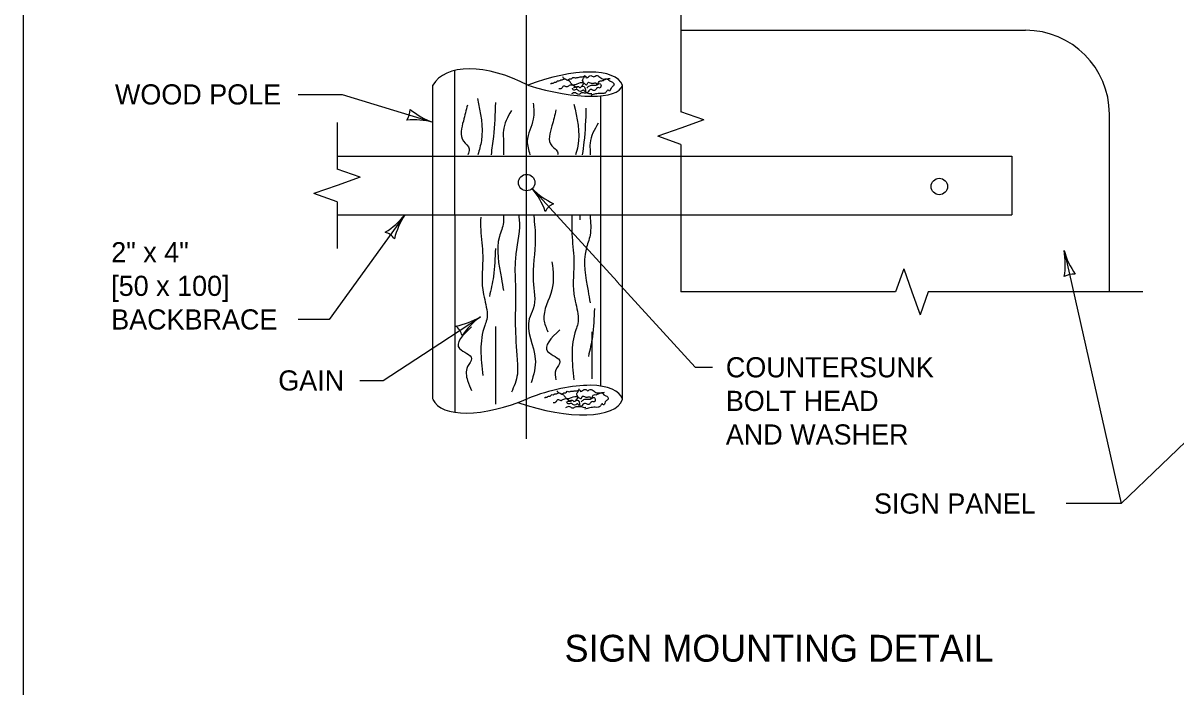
# Model space of a CAD drawing. Extents: x 49991.4 to 50021, y 49987.6 to 50011.4.
# Drawn here: x 50000.336 to 50003.769, y 50003.463 to 50005.439 of the extents above; entities that cross this region are included whole.
import ezdxf

# ---------------------------------------------------------------- set-up
doc = ezdxf.new("R2010")
doc.units = 0
for name, color, linetype in [('Level 1', 7, 'Continuous'), ('Level 2', 7, 'Continuous'), ('Level 3', 7, 'Continuous'), ('Level 4', 7, 'Continuous'), ('Level 5', 7, 'Continuous'), ('Level 6', 7, 'Continuous')]:
    doc.layers.add(name, color=color, linetype=linetype)

msp = doc.modelspace()

# ---------------------------------------------------------------- linework, layer by layer
at = {"layer": 'Level 1'}
for p, q in [((50002.2949, 50005.4172), (50003.321, 50005.4172)), ((50001.6211, 50005.0423), (50001.6211, 50005.2974)), ((50001.5562, 50005.0423), (50001.5562, 50005.2533)), ((50002.0562, 50005.0423), (50002.0562, 50005.2219)), ((50002.1211, 50005.0423), (50002.1211, 50005.2533)), ((50003.571, 50004.6385), (50003.571, 50005.1672)), ((50001.2707, 50005.0423), (50002.2949, 50005.0423)), ((50001.2707, 50004.868), (50002.2949, 50004.868)), ((50001.5562, 50004.3188), (50001.5562, 50004.868)), ((50001.6211, 50004.868), (50001.6211, 50004.2803)), ((50001.9934, 50004.8648), (50001.9942, 50004.8526)), ((50002.0562, 50004.3583), (50002.0562, 50004.868)), ((50002.1211, 50004.3189), (50002.1211, 50004.868))]:
    msp.add_line(p, q, dxfattribs=at)
msp.add_lwpolyline([(50008.6146, 50011.2628), (50000.3356, 50011.2628), (50000.3356, 50000.0624), (50008.6146, 50000.0624)], close=True, dxfattribs=at)
for centre in [(50001.8354, 50004.9639), (50003.0644, 50004.9522)]:
    msp.add_circle(centre, 0.0245, dxfattribs=at)
msp.add_arc((50003.321, 50005.1672), 0.25, 0, 90, dxfattribs=at)
for centre, major_axis, ratio, start_param, end_param in [((50001.7754, 50005.1356), (-0.2192, 0.1177), 0.537084, 4.712389, 6.283185), ((50001.8754, 50005.1582), (0.2457, 0.0951), 0.387082, 0, 1.570796), ((50001.8626, 50005.3321), (0.2585, -0.0788), 0.304673, 4.712389, 6.283185), ((50001.8747, 50004.226), (0.2457, 0.0951), 0.387082, 6.260938, 7.84809), ((50001.7958, 50004.4224), (-0.2396, -0.1036), 0.420526, 0.000916, 1.570796), ((50001.8445, 50004.4166), (0.2766, -0.0977), 0.384401, 4.720139, 6.283852)]:
    msp.add_ellipse(centre, major_axis=major_axis, ratio=ratio, start_param=start_param, end_param=end_param, dxfattribs=at)
for points in [[(50001.9083, 50005.2565), (50001.9083, 50005.2594), (50001.914, 50005.2594), (50001.9183, 50005.2623), (50001.9227, 50005.2623), (50001.927, 50005.2666), (50001.9313, 50005.2666), (50001.9371, 50005.2695), (50001.9414, 50005.2695), (50001.9501, 50005.2723), (50001.9587, 50005.2681), (50001.9631, 50005.2723), (50001.9688, 50005.2723), (50001.9731, 50005.2767), (50001.9804, 50005.2753), (50001.9846, 50005.2767), (50001.989, 50005.2767), (50001.9948, 50005.2781), (50001.9991, 50005.2781), (50002.0049, 50005.2796), (50002.0121, 50005.2796), (50002.0121, 50005.2767), (50002.0164, 50005.2767), (50002.0221, 50005.281), (50002.0308, 50005.281), (50002.0351, 50005.2781), (50002.0394, 50005.281), (50002.0509, 50005.2796), (50002.0611, 50005.2723), (50002.0726, 50005.2723), (50002.0784, 50005.2709), (50002.0827, 50005.2666), (50002.0913, 50005.2623), (50002.0957, 50005.2551), (50002.0942, 50005.2522), (50002.087, 50005.245), (50002.0812, 50005.2363), (50002.0784, 50005.2392), (50002.0726, 50005.2335), (50002.0654, 50005.2291), (50002.0567, 50005.2291), (50002.0409, 50005.2277), (50002.0265, 50005.2233)], [(50001.9313, 50005.2436), (50001.94, 50005.245), (50001.9458, 50005.2522), (50001.9544, 50005.2493), (50001.9631, 50005.2536), (50001.976, 50005.2551), (50001.9861, 50005.258), (50002.0063, 50005.2594), (50002.0149, 50005.2551), (50002.0193, 50005.2623), (50002.025, 50005.2608), (50002.0336, 50005.2594), (50002.0423, 50005.2594), (50002.0438, 50005.2551), (50002.0495, 50005.258), (50002.0539, 50005.258), (50002.0567, 50005.2493), (50002.0539, 50005.245), (50002.0495, 50005.2464), (50002.0438, 50005.2436), (50002.038, 50005.2378), (50002.025, 50005.2407), (50002.0164, 50005.232), (50002.0049, 50005.2306), (50001.9991, 50005.2306), (50001.9904, 50005.2263), (50001.9818, 50005.2306), (50001.9688, 50005.2277)], [(50001.9861, 50005.245), (50001.9688, 50005.258), (50001.9631, 50005.2652), (50001.9486, 50005.2723), (50001.9428, 50005.2781)], [(50002.0005, 50005.2508), (50002.0049, 50005.2608), (50002.002, 50005.2681), (50002.0063, 50005.2767), (50002.0091, 50005.2839)], [(50002.0149, 50005.245), (50002.0207, 50005.2508), (50002.0322, 50005.2536), (50002.0452, 50005.2551), (50002.0539, 50005.2666), (50002.0596, 50005.2666), (50002.0639, 50005.2681), (50002.074, 50005.2723), (50002.0842, 50005.2738)], [(50001.9746, 50005.2464), (50001.9804, 50005.2478), (50001.9904, 50005.2493), (50001.9933, 50005.2464), (50001.9991, 50005.2493), (50002.0063, 50005.2493), (50002.0091, 50005.2349), (50002.0034, 50005.2392), (50001.9991, 50005.2363), (50001.9919, 50005.2363), (50001.9846, 50005.2407), (50001.976, 50005.2392), (50001.9731, 50005.2421), (50001.9717, 50005.245)], [(50002.0106, 50005.2349), (50002.0207, 50005.2291), (50002.0294, 50005.2291)], [(50001.6588, 50005.1946), (50001.6469, 50005.147), (50001.6469, 50005.0875), (50001.6647, 50005.0638), (50001.6602, 50005.0468)], [(50001.6888, 50005.2136), (50001.7007, 50005.0887), (50001.6902, 50005.0468)], [(50001.7423, 50005.2017), (50001.7364, 50005.1006), (50001.7293, 50005.0468)], [(50001.8552, 50005.2003), (50001.8552, 50005.1527), (50001.8374, 50005.0873), (50001.8454, 50005.0468)], [(50001.9761, 50005.1977), (50001.988, 50005.0728), (50001.9814, 50005.0468)], [(50001.7899, 50005.1779), (50001.7661, 50005.1185), (50001.7661, 50005.0947), (50001.7661, 50005.0468)], [(50001.9226, 50005.1799), (50001.9107, 50005.1323), (50001.9107, 50005.0728), (50001.9285, 50005.0491), (50001.9278, 50005.0468)], [(50002.0121, 50005.1856), (50002.0061, 50005.0845), (50002.0011, 50005.0468)], [(50002.0481, 50005.1406), (50002.0243, 50005.0812), (50002.0243, 50005.0574), (50002.0243, 50005.0468)], [(50001.6986, 50004.8611), (50001.6986, 50004.8235), (50001.7046, 50004.7462), (50001.7046, 50004.6451), (50001.7165, 50004.5857), (50001.7165, 50004.5559), (50001.7105, 50004.5381), (50001.7046, 50004.3895)], [(50001.7661, 50004.8648), (50001.7661, 50004.845), (50001.7542, 50004.8034), (50001.7601, 50004.6785), (50001.7661, 50004.6429)], [(50001.812, 50004.8648), (50001.8137, 50004.845), (50001.8018, 50004.738), (50001.8018, 50004.6607), (50001.8018, 50004.5834), (50001.8018, 50004.5299), (50001.8077, 50004.4229), (50001.8077, 50004.3932), (50001.7899, 50004.3397)], [(50001.8565, 50004.8648), (50001.8611, 50004.796), (50001.8552, 50004.6712), (50001.8552, 50004.5879), (50001.8433, 50004.5582), (50001.8611, 50004.4393), (50001.8493, 50004.3679)], [(50001.9701, 50004.8648), (50001.9701, 50004.8112), (50001.9761, 50004.734), (50001.9761, 50004.6329), (50001.988, 50004.5735), (50001.988, 50004.5437), (50001.982, 50004.5259), (50001.9761, 50004.3772)], [(50002.0243, 50004.8648), (50002.0243, 50004.8076), (50002.0124, 50004.766), (50002.0184, 50004.6412), (50002.0243, 50004.6056)], [(50001.7423, 50004.7677), (50001.7364, 50004.6845), (50001.7245, 50004.625)], [(50001.9107, 50004.728), (50001.9107, 50004.6448), (50001.8869, 50004.5556), (50001.8988, 50004.5199)], [(50002.0373, 50004.589), (50002.0313, 50004.5058), (50002.0194, 50004.4463)], [(50001.6714, 50004.535), (50001.6357, 50004.4696), (50001.6714, 50004.4399), (50001.6595, 50004.4161), (50001.6595, 50004.3745), (50001.6714, 50004.3448)], [(50001.7423, 50004.5358), (50001.7423, 50004.5002), (50001.7423, 50004.4407), (50001.7423, 50004.3753), (50001.7423, 50004.3456), (50001.7423, 50004.3159), (50001.7423, 50004.304)], [(50001.9345, 50004.5259), (50001.8988, 50004.4605), (50001.9345, 50004.4307), (50001.9226, 50004.407), (50001.9226, 50004.3768)], [(50002.0296, 50004.5199), (50002.0296, 50004.4843), (50002.0296, 50004.4248), (50002.0296, 50004.3798)], [(50001.8909, 50004.3224), (50001.8909, 50004.3254), (50001.8967, 50004.3254), (50001.901, 50004.3282), (50001.9053, 50004.3282), (50001.9096, 50004.3326), (50001.914, 50004.3326), (50001.9198, 50004.3354), (50001.9241, 50004.3354), (50001.9327, 50004.3383), (50001.9414, 50004.334), (50001.9457, 50004.3383), (50001.9514, 50004.3383), (50001.9558, 50004.3427), (50001.963, 50004.3412), (50001.9673, 50004.3427), (50001.9716, 50004.3427), (50001.9774, 50004.3441), (50001.9817, 50004.3441), (50001.9875, 50004.3455), (50001.9947, 50004.3455), (50001.9947, 50004.3427), (50001.999, 50004.3427), (50002.0048, 50004.3469), (50002.0134, 50004.3469), (50002.0178, 50004.3441), (50002.0221, 50004.3469), (50002.0336, 50004.3455), (50002.0437, 50004.3383), (50002.0552, 50004.3383), (50002.061, 50004.3369), (50002.0653, 50004.3326), (50002.0739, 50004.3282), (50002.0783, 50004.321), (50002.0769, 50004.3181), (50002.0697, 50004.3109), (50002.0639, 50004.3023), (50002.061, 50004.3051), (50002.0552, 50004.2994), (50002.048, 50004.2951), (50002.0394, 50004.2951), (50002.0235, 50004.2936), (50002.0091, 50004.2893)], [(50001.914, 50004.3095), (50001.9226, 50004.3109), (50001.9284, 50004.3181), (50001.9371, 50004.3153), (50001.9457, 50004.3196), (50001.9586, 50004.321), (50001.9688, 50004.3239), (50001.9889, 50004.3254), (50001.9976, 50004.321), (50002.0019, 50004.3282), (50002.0076, 50004.3268), (50002.0163, 50004.3254), (50002.0249, 50004.3254), (50002.0264, 50004.321), (50002.0322, 50004.3239), (50002.0365, 50004.3239), (50002.0394, 50004.3153), (50002.0365, 50004.3109), (50002.0322, 50004.3124), (50002.0264, 50004.3095), (50002.0206, 50004.3037), (50002.0076, 50004.3066), (50001.999, 50004.298), (50001.9875, 50004.2965), (50001.9817, 50004.2965), (50001.9731, 50004.2922), (50001.9644, 50004.2965), (50001.9514, 50004.2936)], [(50001.9688, 50004.3109), (50001.9514, 50004.3239), (50001.9457, 50004.3311), (50001.9313, 50004.3383), (50001.9255, 50004.3441)], [(50001.9831, 50004.3167), (50001.9875, 50004.3268), (50001.9846, 50004.334), (50001.9889, 50004.3427), (50001.9918, 50004.3499)], [(50001.9976, 50004.3109), (50002.0034, 50004.3167), (50002.0149, 50004.3196), (50002.0279, 50004.321), (50002.0365, 50004.3326), (50002.0423, 50004.3326), (50002.0466, 50004.334), (50002.0567, 50004.3383), (50002.0668, 50004.3398)], [(50001.9572, 50004.3124), (50001.963, 50004.3138), (50001.9731, 50004.3153), (50001.9759, 50004.3124), (50001.9817, 50004.3153), (50001.9889, 50004.3153), (50001.9918, 50004.3009), (50001.9861, 50004.3051), (50001.9817, 50004.3023), (50001.9745, 50004.3023), (50001.9673, 50004.3066), (50001.9586, 50004.3051), (50001.9558, 50004.3081), (50001.9544, 50004.3109)], [(50001.9933, 50004.3009), (50002.0034, 50004.2951), (50002.012, 50004.2951)]]:
    msp.add_spline(points, degree=3, dxfattribs=at)
at = {"layer": 'Level 3'}
for p, q in [((50001.155, 50005.2263), (50001.2857, 50005.2263)), ((50001.2857, 50005.2263), (50001.5562, 50005.1434)), ((50002.1046, 50004.6692), (50001.8519, 50004.9458)), ((50001.4726, 50004.868), (50001.2475, 50004.5566)), ((50003.436, 50004.7618), (50003.606, 50004.0087)), ((50002.3377, 50004.4142), (50002.1042, 50004.6697)), ((50001.2475, 50004.5566), (50001.155, 50004.5566)), ((50001.5768, 50004.4854), (50001.6975, 50004.5646)), ((50004.1481, 50004.5291), (50003.606, 50004.0087)), ((50001.4085, 50004.375), (50001.5768, 50004.4854)), ((50002.3377, 50004.4142), (50002.3887, 50004.4142)), ((50001.3387, 50004.375), (50001.4085, 50004.375)), ((50003.606, 50004.0087), (50003.4427, 50004.0087))]:
    msp.add_line(p, q, dxfattribs=at)
for centre, radius, start, end in [((50001.4336, 50005.1809), 0.0548, 325.0945, 0.8168), ((50001.6301, 50005.3531), 0.2223, 230.4117, 250.5952), ((50001.499, 50004.9175), 0.233, 75.7829, 95.0328), ((50001.6818, 50004.8027), 0.2223, 19.8739, 40.0574), ((50002.016, 50005.1113), 0.233, 225.2452, 244.4951), ((50001.9384, 50004.8511), 0.0548, 114.5567, 150.2791), ((50001.2979, 50005.0056), 0.2223, 301.5942, 321.7777), ((50001.6679, 50004.741), 0.233, 146.9655, 166.2153), ((50001.3975, 50004.7641), 0.0548, 36.277, 71.9994), ((50003.2173, 50004.7218), 0.2223, 350.1764, 10.3599), ((50003.6605, 50004.8243), 0.233, 195.5477, 214.7975), ((50003.4642, 50004.6367), 0.0548, 84.8592, 120.5816), ((50001.5833, 50004.7553), 0.2223, 280.7278, 300.9113), ((50001.5833, 50004.7553), 0.2223, 280.7278, 300.9113), ((50001.5903, 50004.4943), 0.0548, 15.4106, 51.133), ((50001.5903, 50004.4943), 0.0548, 15.4106, 51.133), ((50001.8348, 50004.3763), 0.233, 126.0991, 145.3489), ((50001.8348, 50004.3763), 0.233, 126.0991, 145.3489)]:
    msp.add_arc(centre, radius, start, end, dxfattribs=at)
at = {"layer": 'Level 4'}
for p, q in [((50001.5562, 50004.868), (50001.5562, 50005.0423)), ((50001.6211, 50004.868), (50001.6211, 50005.0423)), ((50002.0562, 50004.868), (50002.0562, 50005.0423)), ((50002.1211, 50004.868), (50002.1211, 50005.0423)), ((50002.2949, 50005.0423), (50003.2808, 50005.0423)), ((50003.2808, 50005.0423), (50003.2808, 50004.868)), ((50002.2949, 50004.868), (50003.2808, 50004.868))]:
    msp.add_line(p, q, dxfattribs=at)
at = {"layer": 'Level 5'}
msp.add_line((50001.8354, 50004.2009), (50001.8354, 50006.3601), dxfattribs=at)
at = {"layer": 'Level 6'}
for p, q in [((50002.2949, 50005.5172), (50002.2949, 50005.1746)), ((50002.3635, 50005.1503), (50002.2949, 50005.1746)), ((50001.2707, 50005.1423), (50001.2707, 50005.0038)), ((50002.2949, 50005.126), (50002.2263, 50005.1017)), ((50002.3635, 50005.1503), (50002.2949, 50005.126)), ((50002.2949, 50005.0774), (50002.2263, 50005.1017)), ((50002.2949, 50005.0774), (50002.2949, 50004.6385)), ((50001.3393, 50004.9795), (50001.2707, 50005.0038)), ((50001.2707, 50004.9552), (50001.2021, 50004.9309)), ((50001.3393, 50004.9795), (50001.2707, 50004.9552)), ((50001.2707, 50004.9066), (50001.2021, 50004.9309)), ((50001.2707, 50004.9066), (50001.2707, 50004.768)), ((50002.9586, 50004.707), (50002.9343, 50004.6385)), ((50002.9586, 50004.707), (50002.9829, 50004.6385)), ((50002.9343, 50004.6385), (50002.2949, 50004.6385)), ((50002.9829, 50004.6385), (50003.0072, 50004.57)), ((50003.0315, 50004.6385), (50003.0072, 50004.57)), ((50003.4238, 50004.6385), (50003.0315, 50004.6385)), ((50003.671, 50004.6385), (50003.4238, 50004.6385))]:
    msp.add_line(p, q, dxfattribs=at)

# ---------------------------------------------------------------- texts
at = {"layer": 'Level 2'}
for s, height, p in [('WOOD POLE', 0.06, (50000.6093, 50005.1963)), ('2" x 4"', 0.06, (50000.5982, 50004.7266)), ('[50 x 100]', 0.06, (50000.5982, 50004.6266)), ('BACKBRACE', 0.06, (50000.5982, 50004.5266)), ('COUNTERSUNK ', 0.06, (50002.4287, 50004.3842)), ('GAIN', 0.06, (50001.0957, 50004.345)), ('BOLT HEAD', 0.06, (50002.4287, 50004.2842)), ('AND WASHER', 0.06, (50002.4287, 50004.1842)), ('SIGN PANEL', 0.06, (50002.8699, 50003.9787)), ('SIGN MOUNTING DETAIL', 0.08, (50001.9484, 50003.538))]:
    msp.add_text(s, height=height, dxfattribs=at).set_placement(p)

doc.saveas('drawing.dxf')
